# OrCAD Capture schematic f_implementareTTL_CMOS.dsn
size B
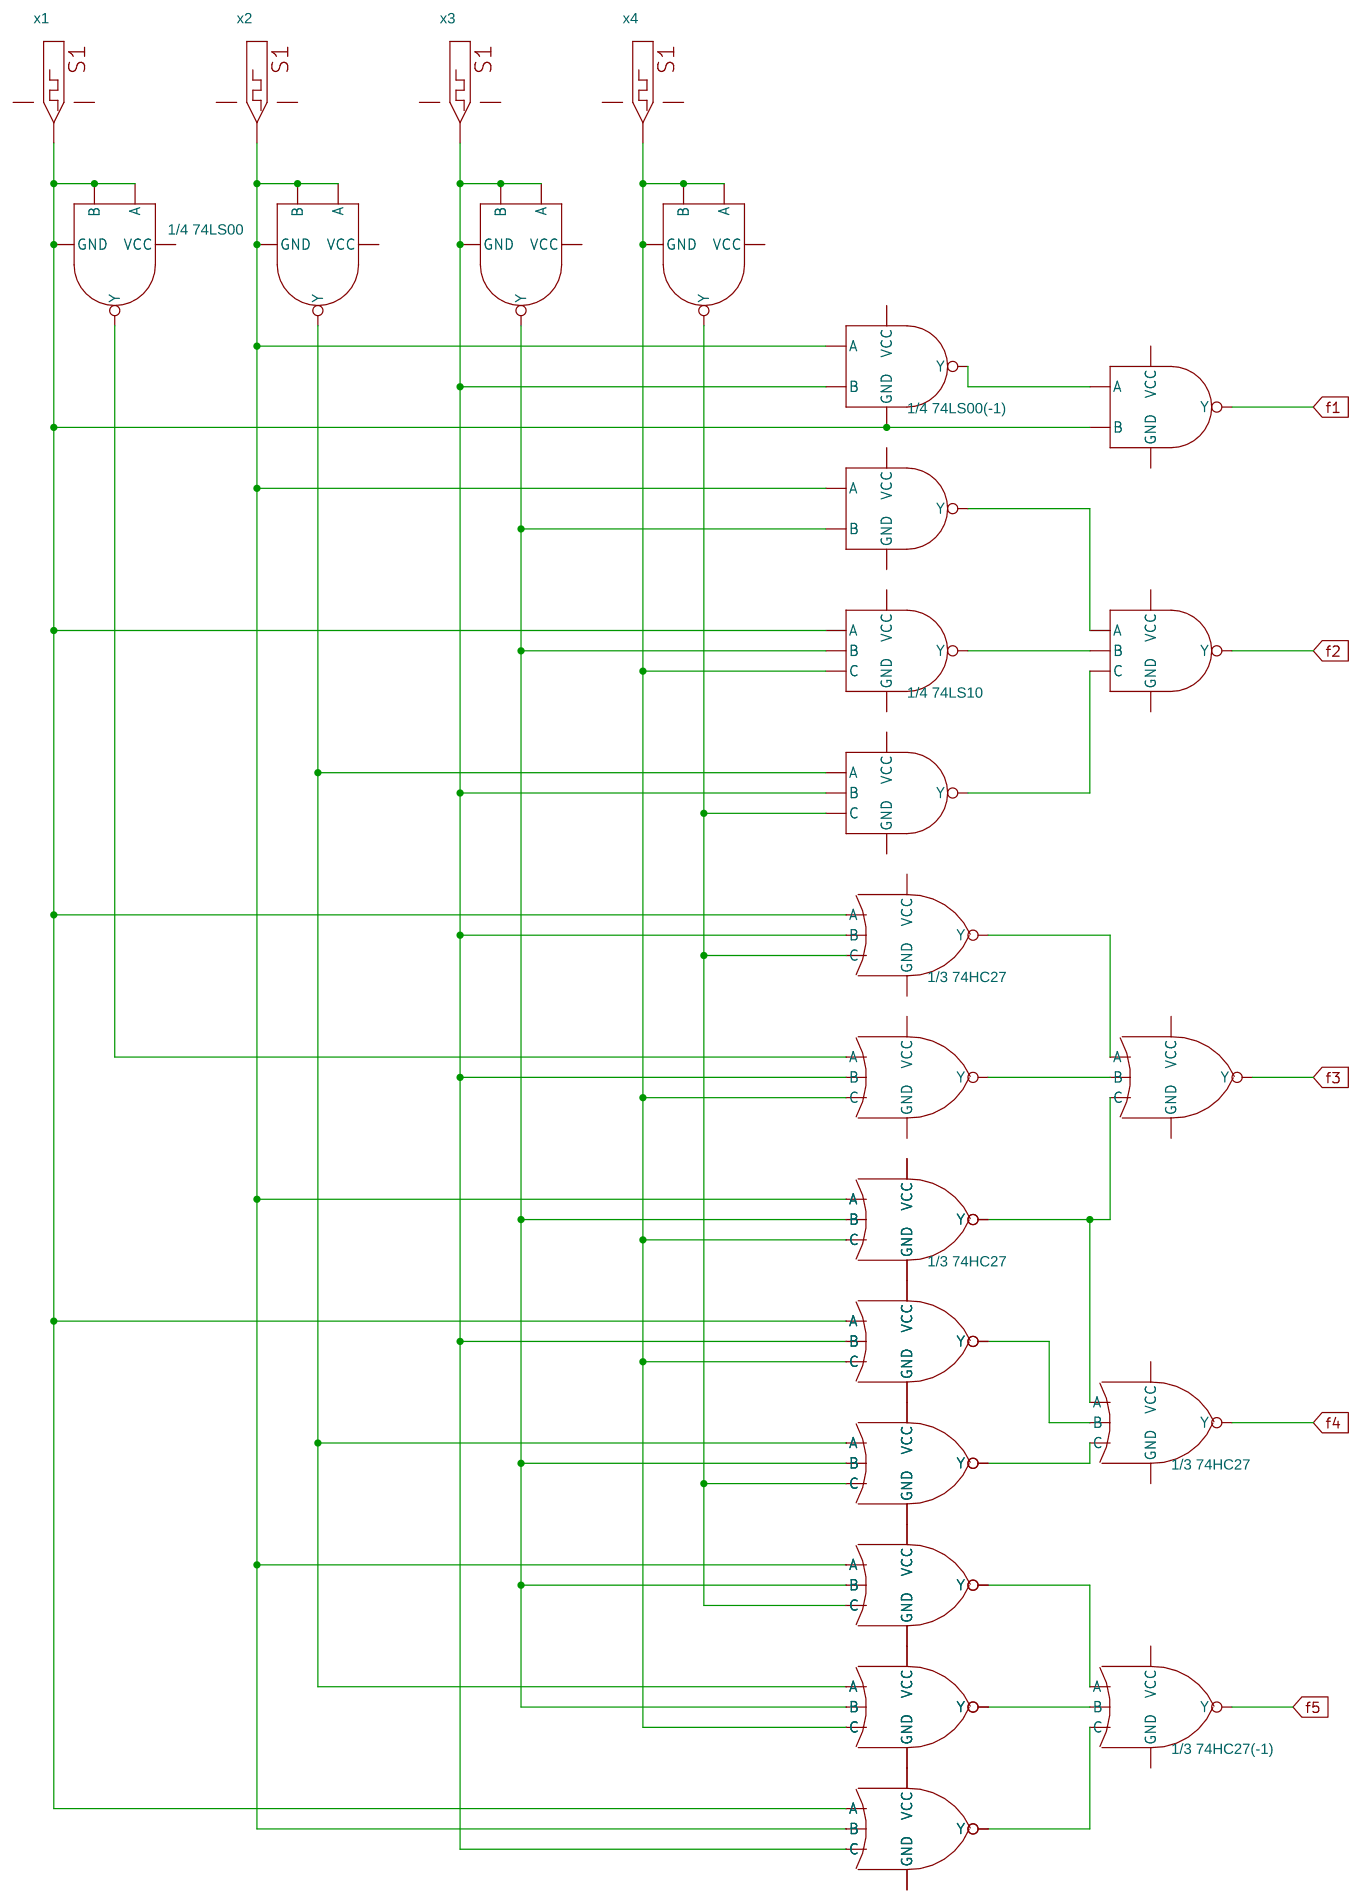
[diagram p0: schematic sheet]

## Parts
U20  1/4 74LS00(-1)  [DIP.100/14/W.300/L.800]  (section A)
U21  1/4 74LS10  [DIP.100/14/W.300/L.800]  (section A)
U22  1/3 74HC27  [DIP.100/14/W.300/L.800]  (section A)
U23  1/4 74LS00  [DIP.100/14/W.300/L.800]  (sections A,B,C,D)
U24  1/4 74LS00(-1)  [DIP.100/14/W.300/L.800]  (sections A,B)
U25  1/4 74LS10  [DIP.100/14/W.300/L.800]  (sections A,B)
U26  1/3 74HC27  [DIP.100/14/W.300/L.800]  (sections A,B,C)
U27  1/3 74HC27  [DIP.100/14/W.300/L.800]  (sections A,B,C)
U28  1/3 74HC27  [DIP.100/14/W.300/L.800]  (section C)
U29  1/3 74HC27  [DIP.100/14/W.300/L.800]  (section C)
U30  1/3 74HC27  [DIP.100/14/W.300/L.800]  (section C)
U31  1/3 74HC27(-1)  [DIP.100/14/W.300/L.800]  (section C)
x1  DigStim1
x2  DigStim1
x3  DigStim1
x4  DigStim1

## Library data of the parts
U20 U23 U24 = 74LS00
U21 U25 = 74LS10
U22 U26-U31 = 74HC27
x1-x4 = DigStim1

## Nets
GND: U20.7(GND) U21.7(GND) U22.7(GND) U23.7(GND) U24.7(GND) U25.7(GND) U26.7(GND) U27.7(GND) U28.7(GND) U29.7(GND) U30.7(GND) U31.7(GND) x1.3(GND) x2.3(GND) x3.3(GND) x4.3(GND)
VCC: U20.14(VCC) U21.14(VCC) U22.14(VCC) U23.14(VCC) U24.14(VCC) U25.14(VCC) U26.14(VCC) U27.14(VCC) U28.14(VCC) U29.14(VCC) U30.14(VCC) U31.14(VCC) x1.2(VCC) x2.2(VCC) x3.2(VCC) x4.2(VCC)
f1: U24.6(Y)
f2: U25.6(Y)
f3: U26.6(Y)
f4: U27.8(Y)
f5: U31.8(Y)
N18718: U21.13(C) U23.12(A) U23.13(B) U26.11(C) U26.13(C) U27.13(C) U29.11(C) x4.OUT
N18730: U20.2(B) U22.2(B) U23.9(A) U23.10(B) U25.2(B) U26.2(B) U27.2(B) U30.11(C) x3.OUT
N18742: U20.1(A) U23.4(A) U23.5(B) U24.1(A) U26.9(A) U28.9(A) U30.10(B) x2.OUT
N18754: U21.1(A) U22.1(A) U23.1(A) U23.2(B) U24.5(B) U27.1(A) U30.9(A) x1.OUT
N18868: U21.2(B) U23.8(Y) U24.2(B) U26.10(B) U27.4(B) U28.10(B) U29.10(B)
N18996: U23.6(Y) U25.1(A) U27.3(A) U29.9(A)
N19012: U22.13(C) U23.11(Y) U25.13(C) U27.5(C) U28.11(C)
N19044: U25.5(C) U25.12(Y)
N19052: U24.3(Y) U25.3(A)
N19060: U21.12(Y) U25.4(B)
N19068: U23.3(Y) U26.1(A)
N19168: U20.3(Y) U24.4(A)
N21834: U22.12(Y) U26.3(A)
N22075: U26.4(B) U26.12(Y)
N22085: U26.5(C) U26.8(Y) U27.9(A)
N22371: U27.10(B) U27.12(Y)
N22386: U27.6(Y) U27.11(C)
N23125: U29.8(Y) U31.10(B)
N23135: U28.8(Y) U31.9(A)
N23142: U30.8(Y) U31.11(C)
